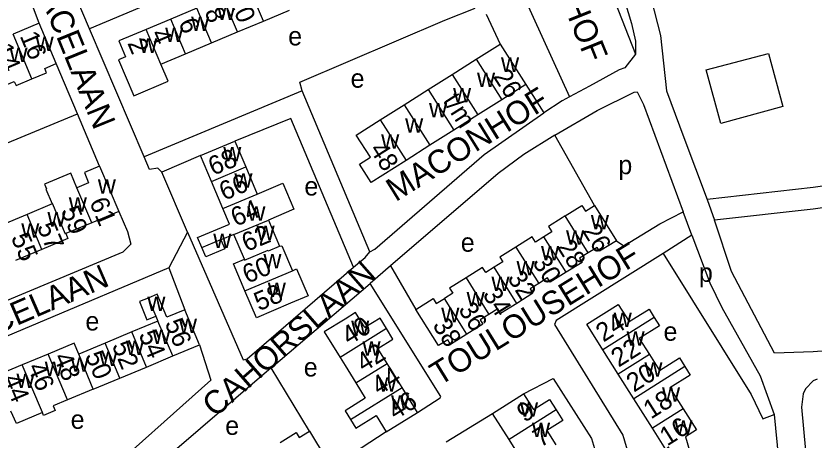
# Model space of a CAD drawing. Extents: x 157768 to 159790, y 387230 to 389604.
# Drawn here: x 158929.7 to 159100.2, y 388092.2 to 388182.9 of the extents above; entities that cross this region are included whole.
import ezdxf

# ---------------------------------------------------------------- set-up
doc = ezdxf.new("R2010")
doc.units = 0
for name, color, linetype in [('BLT_Basislijn', 7, 'Continuous'), ('BLT_Bebouwing', 7, 'Continuous'), ('BLT_Centroide', 7, 'Continuous'), ('BLT_Huisnummer', 7, 'Continuous'), ('BLT_Huisnummer_ tussenligend', 7, 'Continuous'), ('BLT_Huisnummer_reeks', 7, 'Continuous'), ('BLT_Onderverdeling_panden', 7, 'Continuous'), ('BLT_Straatnaam', 7, 'Continuous')]:
    doc.layers.add(name, color=color, linetype=linetype)

msp = doc.modelspace()

# ---------------------------------------------------------------- linework, layer by layer
at = {"layer": 'BLT_Basislijn'}
for p, q in [((158934.65, 388181.31), (158931.96, 388188.46)), ((158945.39, 388180.09), (158941.93, 388188.37)), ((159030.18, 388183.24), (159033.13, 388176.86)), ((158957.11, 388152.75), (158945.39, 388180.09)), ((158942.82, 388161.96), (158938.3, 388172.66)), ((159058.61, 388171.35), (159052.21, 388167.85)), ((159038.63, 388168.18), (159042.48, 388162.15)), ((159052.21, 388167.85), (159047.96, 388165.55)), ((158990.83, 388166.82), (158957.11, 388152.75)), ((159005.33, 388132.44), (158990.83, 388166.82)), ((158894.82, 388142.12), (158942.82, 388161.96)), ((158947.55, 388150.74), (158942.82, 388161.96)), ((158988.42, 388160.94), (158976.47, 388156.1)), ((159001.84, 388129.12), (158988.42, 388160.94)), ((159053.3, 388142.34), (159044.85, 388157.37)), ((158969.13, 388153), (158960.86, 388149.49)), ((159077.37, 388143.65), (159078.97, 388139.21)), ((159074.11, 388135.96), (159072.25, 388140.95)), ((159074.11, 388135.96), (159067.96, 388132.08)), ((159067.96, 388132.08), (159086.78, 388101.95)), ((158962.38, 388128.99), (158965.76, 388120.04)), ((159009.71, 388129.44), (159005.38, 388125.65)), ((159009.71, 388129.44), (159015.12, 388120.11)), ((158984.21, 388107.6), (159005.38, 388125.65)), ((158984.21, 388107.6), (158954.63, 388082.29)), ((158992.37, 388094.06), (158984.21, 388107.6)), ((159086.78, 388101.95), (159089.26, 388096.72)), ((159021.61, 388091.82), (159031.54, 388097.88)), ((159089.26, 388096.72), (159091.7, 388097.64)), ((159091.7, 388097.64), (159096.84, 388046.05)), ((159008.82, 388093.95), (158997.12, 388086.39))]:
    msp.add_line(p, q, dxfattribs=at)
for points in [[(159083.6, 388219.22), (159100, 388222.27), (159129.92, 388229.22), (159142.28, 388194.61), (159151.8, 388155.41), (159151.99, 388153.74), (159100, 388146.19), (159077.37, 388143.65)], [(159046.13, 388213.86), (159057.65, 388193.09), (159061.21, 388181.27), (159062.09, 388177.47), (159062.06, 388174.72)], [(159016.78, 388210.26), (159001.34, 388203.52), (158998.79, 388202.66), (158945.39, 388180.09)], [(159035.87, 388206.05), (159041.17, 388193.03), (159036.51, 388190.78), (159047.96, 388165.55)], [(159057.76, 388204.65), (159058.45, 388203.43), (159060.99, 388198.76), (159065.43, 388186.51), (159067.44, 388178.65), (159068.67, 388166.84), (159072.42, 388156.85)], [(159050.47, 388192.04), (159054.67, 388193.67), (159062.06, 388174.72)], [(158990.83, 388166.82), (158990.32, 388168.68), (159021.35, 388181.98), (159027.8, 388184.5)], [(159062.06, 388174.72), (159059.8, 388171.8), (159058.61, 388171.35)], [(159080.3, 388159.84), (159077.2, 388171.36), (159090.48, 388174.83)], [(159090.48, 388174.83), (159093.58, 388163.53), (159080.3, 388159.84)], [(159044.85, 388157.37), (159053.89, 388162.63), (159061.81, 388166.55), (159062.44, 388166.61), (159063.76, 388163.91), (159072.25, 388140.95)], [(159047.96, 388165.55), (159046.41, 388164.7), (159042.48, 388162.15)], [(159005.33, 388132.44), (159006.36, 388133.01), (159029.74, 388153.25), (159042.48, 388162.15)], [(159044.85, 388157.37), (159038.21, 388153.21), (159032.74, 388149.15), (159009.71, 388129.44)], [(159072.42, 388156.85), (159077.37, 388143.65)], [(158960.86, 388149.49), (158959.96, 388150.33), (158958.24, 388150.04), (158957.11, 388152.75)], [(158966.33, 388136.61), (158960.86, 388149.49)], [(159164.86, 388122.72), (159154.22, 388147.16), (159151.99, 388148.94), (159100, 388141.57), (159078.97, 388139.21)], [(158951.63, 388141.08), (158953.53, 388136.81), (158954.26, 388134.06), (158952.54, 388132.37), (158906.9, 388113.3)], [(159058, 388134.8), (159059.56, 388133.73), (159067.27, 388138.41), (159072.25, 388140.95)], [(159126.67, 388113.01), (159100, 388111.07), (159091.74, 388110.78), (159082.59, 388128.25), (159078.97, 388139.21)], [(158966.33, 388136.61), (158962.38, 388128.99)], [(158966.33, 388136.61), (158978.25, 388109.34), (158979.1, 388109.58), (159001.84, 388129.12)], [(159074.11, 388135.96), (159077.93, 388125.78), (159080.55, 388120.5), (159088.74, 388105.89), (159091.7, 388097.64)], [(159001.84, 388129.12), (159004.3, 388131.24), (159005.33, 388132.44)], [(159067.96, 388132.08), (159045.15, 388117.74), (159044.78, 388116.92), (159059.35, 388093.23), (159069.9, 388057.42), (159074.64, 388040.12), (159075.12, 388040.01), (159084.5, 388042.66)], [(158962.38, 388128.99), (158906.27, 388105.35)], [(159015.48, 388098.08), (159020.36, 388101.18), (159020.45, 388101.5), (159005.38, 388125.65)], [(158968.9, 388112.54), (158971.35, 388105.01), (158946.75, 388083.04)], [(159038.15, 388102.04), (159044.48, 388105.38), (159052.7, 388092.49), (159057.59, 388076.14), (159058.61, 388071), (159054.88, 388069.7)], [(159100.88, 388105.2), (159100, 388104.85), (159098.37, 388103.16), (159097.88, 388102.09), (159097.57, 388099.2), (159100, 388072.22), (159100.37, 388068.74)]]:
    msp.add_lwpolyline(points, dxfattribs=at)
at = {"layer": 'BLT_Bebouwing'}
for p, q in [((158968.33, 388184.53), (158962.77, 388182.2)), ((158982.57, 388181.77), (158988.12, 388184.1)), ((158934.65, 388181.31), (158929.08, 388178.96)), ((158938.3, 388172.66), (158934.65, 388181.31)), ((158962.77, 388182.2), (158957.53, 388179.99)), ((158977.01, 388179.43), (158982.57, 388181.77)), ((158971.46, 388177.09), (158977.01, 388179.43)), ((158965.9, 388174.76), (158971.46, 388177.09)), ((159028.01, 388173.61), (159033.13, 388176.86)), ((159033.13, 388176.86), (159038.63, 388168.18)), ((158960.65, 388172.55), (158965.9, 388174.76)), ((159022.89, 388170.36), (159028.01, 388173.61)), ((159017.77, 388167.12), (159022.89, 388170.36)), ((159038.63, 388168.18), (159033.51, 388164.93)), ((159012.65, 388163.87), (159017.77, 388167.12)), ((159033.51, 388164.93), (159028.39, 388161.69)), ((159007.53, 388160.63), (159012.65, 388163.87)), ((159028.39, 388161.69), (159023.27, 388158.44)), ((159023.27, 388158.44), (159018.15, 388155.2)), ((159018.15, 388155.2), (159013.03, 388151.95)), ((158947.55, 388150.74), (158951.63, 388141.08)), ((158978.81, 388150.57), (158981.25, 388144.79)), ((158973.91, 388141.68), (158971.47, 388147.46)), ((158937.39, 388142.66), (158932.04, 388140.4)), ((159053.3, 388142.34), (159058, 388134.8)), ((158932.04, 388140.4), (158926.43, 388138.03)), ((158951.63, 388141.08), (158945.87, 388138.65)), ((158983.61, 388139.22), (158985.97, 388133.62)), ((158978.49, 388130.86), (158976.25, 388136.15)), ((158935.19, 388132.93), (158929.59, 388130.57)), ((158968.9, 388112.54), (158965.76, 388120.04)), ((158959.56, 388118.67), (158959.99, 388117.63)), ((158959.99, 388117.63), (158954.42, 388115.3)), ((158954.42, 388115.3), (158948.75, 388112.93)), ((158948.75, 388112.93), (158943.08, 388110.57)), ((158963.23, 388110.17), (158968.9, 388112.54)), ((159058.38, 388106.29), (159055.1, 388111.5)), ((158936.55, 388110.57), (158930.99, 388108.25)), ((158957.55, 388107.8), (158963.23, 388110.17)), ((158930.99, 388108.25), (158925.43, 388105.93)), ((158951.88, 388105.43), (158957.55, 388107.8)), ((159012.18, 388103.39), (159008.99, 388108.55)), ((159061.7, 388101.02), (159058.38, 388106.29)), ((158946.21, 388103.07), (158940.69, 388100.76)), ((159015.48, 388098.08), (159012.18, 388103.39)), ((159031.54, 388097.88), (159038.15, 388102.04)), ((159065.68, 388094.7), (159061.7, 388101.02)), ((159008.82, 388093.95), (159015.48, 388098.08)), ((159035.04, 388092.3), (159031.54, 388097.88)), ((158992.37, 388094.06), (158997.12, 388086.39)), ((159038.39, 388086.99), (159035.04, 388092.3))]:
    msp.add_line(p, q, dxfattribs=at)
for points in [[(158957.53, 388179.99), (158951.66, 388177.52), (158953.1, 388174.11), (158951.6, 388173.49), (158954.84, 388165.8), (158962.19, 388168.89), (158960.65, 388172.55)], [(158933.1, 388169.41), (158936.24, 388170.73), (158935.86, 388171.63), (158938.3, 388172.66)], [(158927.08, 388167.93), (158929.31, 388168.87), (158929.69, 388167.97), (158933.1, 388169.41)], [(159013.03, 388151.95), (159005.59, 388147.23), (159003.09, 388151.17), (159005.41, 388152.64), (159002.41, 388157.38), (159007.53, 388160.63)], [(158969.13, 388153), (158976.47, 388156.1)], [(158976.47, 388156.1), (158978.81, 388150.57)], [(158971.47, 388147.46), (158969.13, 388153)], [(158947.55, 388150.74), (158944.29, 388149.36), (158945.2, 388147.2), (158942.7, 388146.14)], [(158942.7, 388146.14), (158941.39, 388149.26), (158935.77, 388146.89), (158936.2, 388145.87), (158936.06, 388145.82), (158937.39, 388142.66)], [(158981.25, 388144.79), (158986.74, 388147.11), (158989.08, 388141.58), (158983.61, 388139.22)], [(159047.07, 388140.1), (159050.61, 388142.31), (159051.35, 388141.13), (159053.3, 388142.34)], [(158969.41, 388133.33), (158968.5, 388135.49), (158975.33, 388138.34), (158973.91, 388141.68)], [(158945.87, 388138.65), (158940.35, 388136.32)], [(159047.07, 388140.1), (159046.37, 388139.67), (159043.49, 388137.87), (159044.21, 388136.71), (159042.5, 388135.65)], [(158940.35, 388136.32), (158940.79, 388135.29), (158935.19, 388132.93)], [(158976.25, 388136.15), (158973.49, 388134.99)], [(159042.5, 388135.65), (159040.67, 388134.51), (159039.98, 388135.61), (159036.53, 388133.46)], [(158973.49, 388134.99), (158974.29, 388133.1), (158970.22, 388131.38), (158969.41, 388133.33)], [(158985.97, 388133.62), (158986.49, 388133.71), (158988.74, 388128.4)], [(159036.53, 388133.46), (159033.08, 388131.31), (159033.73, 388130.27), (159031.89, 388129.13)], [(159058, 388134.8), (159054.38, 388132.54), (159053.85, 388133.39), (159051.97, 388132.22)], [(159051.97, 388132.22), (159050.1, 388131.05), (159050.64, 388130.18), (159047.23, 388128.06)], [(158978.61, 388124.11), (158976.17, 388129.88), (158978.49, 388130.86)], [(158988.74, 388128.4), (158989.66, 388128.79), (158992.11, 388123), (158988.38, 388121.43), (158981.05, 388118.33), (158978.61, 388124.11)], [(159031.89, 388129.13), (159030.06, 388127.99), (159029.38, 388129.07), (159025.86, 388126.88)], [(159025.86, 388126.88), (159022.33, 388124.68), (159023.02, 388123.57), (159021.23, 388122.46)], [(159047.23, 388128.06), (159043.82, 388125.94), (159043.26, 388126.84), (159041.38, 388125.67)], [(159041.38, 388125.67), (159039.55, 388124.53), (159040.15, 388123.57), (159036.69, 388121.41)], [(158965.76, 388120.04), (158961.95, 388118.45), (158959.88, 388123.38), (158957.9, 388122.55)], [(158957.9, 388122.55), (158956.05, 388121.78), (158957.67, 388117.88), (158959.56, 388118.67)], [(159015.12, 388120.11), (159018.83, 388122.42), (159019.48, 388121.37), (159021.23, 388122.46)], [(159036.69, 388121.41), (159033.24, 388119.26), (159032.64, 388120.22), (159030.74, 388119.04)], [(159026, 388114.79), (159022.55, 388112.65), (159021.94, 388113.63), (159019.94, 388112.38), (159015.12, 388120.11)], [(159055.1, 388111.5), (159051.67, 388116.95), (159058.37, 388121.17), (159060.68, 388117.5), (159064.96, 388120.19), (159066.07, 388118.41)], [(159008.86, 388116.02), (159007.48, 388118.25), (159004.23, 388116.23), (159002.24, 388119.43), (159000, 388118.04), (158995.57, 388115.29), (158998.93, 388109.86)], [(159030.74, 388119.04), (159028.87, 388117.87), (159029.45, 388116.94), (159026, 388114.79)], [(159066.07, 388118.41), (159067.19, 388116.64), (159062.87, 388113.91), (159065.03, 388110.48)], [(159008.99, 388108.55), (159006.99, 388111.77), (159010.24, 388113.79), (159008.86, 388116.02)], [(158943.08, 388110.57), (158942.11, 388112.89), (158936.55, 388110.57)], [(158998.93, 388109.86), (159000, 388108.15), (159002.31, 388104.42)], [(159065.03, 388110.48), (159067.19, 388107.04), (159071.45, 388109.73), (159072.61, 388107.89)], [(159072.61, 388107.89), (159073.77, 388106.05), (159069.43, 388103.32), (159072.26, 388098.84)], [(158946.21, 388103.07), (158951.88, 388105.43)], [(159002.31, 388104.42), (159004.33, 388101.16), (159000, 388098.4), (159001.15, 388096.55)], [(159038.15, 388102.04), (159040.24, 388098.7), (159043.7, 388100.88), (159045.11, 388098.63)], [(158940.69, 388100.76), (158937.65, 388099.49), (158938.07, 388098.49), (158935.57, 388097.44), (158935.32, 388098.05)], [(158935.32, 388098.05), (158929.78, 388095.74), (158928.58, 388098.39)], [(159045.11, 388098.63), (159046.52, 388096.39), (159043.13, 388094.26), (159045.07, 388091.19)], [(159072.26, 388098.84), (159075.07, 388094.36), (159072.74, 388092.9), (159073.61, 388089.96)], [(159001.15, 388096.55), (159002.29, 388094.71), (159006.67, 388097.42), (159008.82, 388093.95)], [(159069.65, 388088.79), (159069.09, 388090.71), (159068.55, 388090.14), (159065.68, 388094.7)], [(158986.15, 388091.67), (158989.57, 388093.79), (158990.22, 388092.73), (158992.37, 388094.06)]]:
    msp.add_lwpolyline(points, dxfattribs=at)
at = {"layer": 'BLT_Onderverdeling_panden'}
for p, q in [((158982.57, 388181.77), (158979.44, 388189.21)), ((158977.01, 388179.43), (158973.88, 388186.87)), ((158971.46, 388177.09), (158968.33, 388184.53)), ((158965.9, 388174.76), (158962.77, 388182.2)), ((158960.65, 388172.55), (158957.53, 388179.99)), ((158933.1, 388169.41), (158929.08, 388178.96)), ((159028.01, 388173.61), (159033.51, 388164.93)), ((159022.89, 388170.36), (159028.39, 388161.69)), ((159017.77, 388167.12), (159023.27, 388158.44)), ((159012.65, 388163.87), (159018.15, 388155.2)), ((159007.53, 388160.63), (159013.03, 388151.95)), ((158971.47, 388147.46), (158978.81, 388150.57)), ((158945.87, 388138.65), (158942.7, 388146.14)), ((158973.91, 388141.68), (158981.25, 388144.79)), ((158935.19, 388132.93), (158932.04, 388140.4)), ((158976.25, 388136.15), (158983.61, 388139.22)), ((159051.97, 388132.22), (159047.07, 388140.1)), ((159047.23, 388128.06), (159042.5, 388135.65)), ((159036.53, 388133.46), (159041.38, 388125.67)), ((158978.61, 388124.11), (158988.74, 388128.4)), ((159036.69, 388121.41), (159031.89, 388129.13)), ((159025.86, 388126.88), (159030.74, 388119.04)), ((158957.9, 388122.55), (158959.56, 388118.67)), ((159026, 388114.79), (159021.23, 388122.46)), ((159066.07, 388118.41), (159055.1, 388111.5)), ((158963.23, 388110.17), (158959.99, 388117.63)), ((158957.55, 388107.8), (158954.42, 388115.3)), ((159008.86, 388116.02), (158998.93, 388109.86)), ((158951.88, 388105.43), (158948.75, 388112.93)), ((158940.69, 388100.76), (158936.55, 388110.57)), ((158946.21, 388103.07), (158943.08, 388110.57)), ((159065.03, 388110.48), (159058.38, 388106.29)), ((158935.32, 388098.05), (158930.99, 388108.25)), ((159002.31, 388104.42), (159008.99, 388108.55)), ((159072.61, 388107.89), (159061.7, 388101.02)), ((159001.15, 388096.55), (159012.18, 388103.39)), ((159045.11, 388098.63), (159035.04, 388092.3)), ((159072.26, 388098.84), (159065.68, 388094.7))]:
    msp.add_line(p, q, dxfattribs=at)
for points in [[(158940.35, 388136.32), (158940.25, 388136.24), (158937.5, 388142.75), (158937.39, 388142.66)], [(158969.41, 388133.33), (158973.46, 388135.05), (158973.49, 388134.99)], [(158978.49, 388130.86), (158978.55, 388130.67), (158983.57, 388132.81), (158983.64, 388132.64), (158985.97, 388133.62)]]:
    msp.add_lwpolyline(points, dxfattribs=at)

# ---------------------------------------------------------------- texts
at = {"layer": 'BLT_Centroide'}
for s, p in [('w', (158972.67, 388181.98)), ('w', (158967.11, 388179.66)), ('w', (158961.56, 388177.31)), ('e', (158987.85, 388176.56)), ('w', (158933.88, 388175.38)), ('w', (158956, 388174.97)), ('w', (158928.3, 388173)), ('w', (159033.33, 388170.91)), ('e', (159001.19, 388167.52)), ('w', (159028.2, 388167.66)), ('w', (159023.08, 388164.41)), ('w', (159017.95, 388161.16)), ('w', (159012.84, 388157.91)), ('w', (159007.72, 388154.47)), ('w', (158973.97, 388151.78)), ('p', (159058.4, 388149.02)), ('w', (158976.36, 388146.12)), ('w', (158947.17, 388144.88)), ('e', (158991.31, 388144.47)), ('w', (158940.97, 388141)), ('w', (158979.12, 388139.06)), ('w', (158936.41, 388137.84)), ('w', (159052.53, 388137.22)), ('w', (158930.81, 388135.48)), ('w', (158981.09, 388134.94)), ('w', (159047.23, 388133.94)), ('w', (158971.84, 388133.22)), ('e', (159024.73, 388132.45)), ('w', (159041.88, 388130.61)), ('w', (158982.55, 388128.91)), ('w', (159036.64, 388127.39)), ('p', (159075.61, 388126.01)), ('w', (159031.28, 388124.06)), ('w', (158983.49, 388122.78)), ('w', (159025.98, 388120.75)), ('w', (158957.75, 388119.78)), ('w', (159020.56, 388117.39)), ('e', (158944.52, 388115.62)), ('w', (158964.5, 388115.09)), ('w', (159057.41, 388116.34)), ('w', (159001.31, 388114.66)), ('e', (159068.05, 388113.42)), ('w', (158958.83, 388112.75)), ('w', (159060.15, 388112.34)), ('w', (158953.16, 388110.38)), ('w', (159003.73, 388110.22)), ('w', (158941.38, 388106.83)), ('w', (158947.48, 388108)), ('w', (158935.84, 388105.86)), ('e', (158991.18, 388105.78)), ('w', (159063.97, 388105.75)), ('w', (158929.78, 388103.33)), ('w', (159007.15, 388102.56)), ('w', (159067.73, 388100.41)), ('w', (159009.84, 388098.69)), ('w', (159037.38, 388097.16)), ('e', (158941.37, 388094.59)), ('e', (158974.4, 388093.3)), ('w', (159039.95, 388092.81)), ('w', (159070.38, 388093.33))]:
    msp.add_text(s, height=4, dxfattribs=at).set_placement(p)
at = {"layer": 'BLT_Huisnummer'}
for s, rotation, p in [('10', 292.8099, (158975.07, 388186.5)), ('6', 292.8099, (158964.34, 388181.45)), ('16', 292.8691, (158930.44, 388178.6)), ('2', 292.8099, (158953.44, 388177.08)), ('68', 22.9025, (158971.83, 388148.66)), ('61', 292.87, (158945.3, 388143.09)), ('26', 301.9112, (159050.57, 388136.92)), ('62', 22.9025, (158978.97, 388132.37)), ('55', 292.87, (158928.55, 388135.51)), ('30', 301.9112, (159039.92, 388130.21)), ('58', 22.9025, (158981.6, 388119.71)), ('34', 301.9112, (159029.29, 388123.33)), ('56', 292.6717, (158961.4, 388117.21)), ('40', 31.7921, (159000.88, 388112.36)), ('38', 301.9112, (159018.58, 388116.74)), ('24', 32.2062, (159055.21, 388113.01)), ('50', 292.6717, (158944.41, 388110.28)), ('46', 292.6717, (158932.09, 388107.8)), ('46', 31.79, (159010.74, 388096.38)), ('18', 32.2062, (159065.36, 388096.56)), ('9', 32.1542, (159038.34, 388095.84))]:
    msp.add_text(s, height=4, rotation=rotation, dxfattribs=at).set_placement(p)
at = {"layer": 'BLT_Huisnummer_ tussenligend'}
for s, rotation, p in [('8', 292.8099, (158969.9, 388183.76)), ('4', 292.8099, (158958.38, 388179.11)), ('14', 292.8691, (158924.88, 388176.04)), ('66', 22.9025, (158974.17, 388143.32)), ('59', 292.87, (158939.2, 388141.23)), ('64', 22.9025, (158976.64, 388137.77)), ('57', 292.87, (158934.1, 388137.84)), ('28', 301.9112, (159045.17, 388133.51)), ('60', 22.9025, (158979.13, 388125.58)), ('32', 301.9112, (159034.58, 388126.85)), ('36', 301.9112, (159024.1, 388120.13)), ('54', 292.6717, (158955.83, 388114.76)), ('52', 292.6717, (158950.12, 388112.43)), ('22', 32.2062, (159058.46, 388107.65)), ('42', 31.7921, (159003.97, 388106.61)), ('48', 292.6717, (158937.65, 388109.95)), ('44', 31.7921, (159007.24, 388101.67)), ('20', 32.2062, (159061.73, 388102.3)), ('44', 292.6717, (158926.74, 388105.34)), ('16', 32.2062, (159068.84, 388090.8)), ('7', 32.1542, (159041.76, 388090.5))]:
    msp.add_text(s, height=4, rotation=rotation, dxfattribs=at).set_placement(p)
at = {"layer": 'BLT_Huisnummer_reeks'}
for s, p in [('26', (159031.52, 388169.94)), ('t/m', (159020.78, 388164.77)), ('48', (159005.13, 388154.33))]:
    msp.add_text(s, height=4, rotation=302.3767, dxfattribs=at).set_placement(p)
at = {"layer": 'BLT_Straatnaam'}
for s, rotation, p in [('MACONHOF', 291.9115, (159037.09, 388208.73)), ('ALSACELAAN', 292.1247, (158929.95, 388198.86)), ('MACONHOF', 31.9115, (159010.82, 388143.03)), ('TOULOUSEHOF', 31.7241, (159020.16, 388103.68)), ('CAHORSLAAN', 41.2139, (158972.23, 388096.86)), ('ALSACELAAN', 23.4636, (158909.72, 388107.84))]:
    msp.add_text(s, height=5, rotation=rotation, dxfattribs=at).set_placement(p)

doc.saveas('drawing.dxf')
